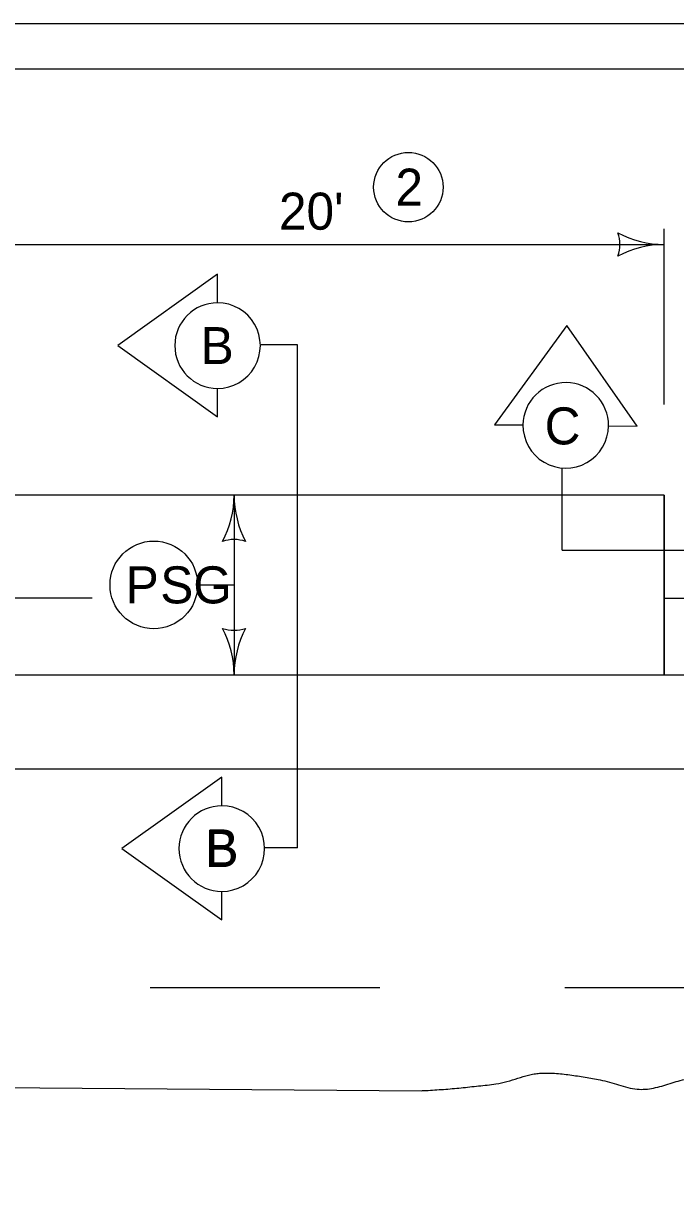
# Model space of a CAD drawing. Extents: x 8045 to 81668, y 6217 to 16762.
# Drawn here: x 11528 to 11810, y 9440 to 9944 of the extents above; entities that cross this region are included whole.
import ezdxf

# ---------------------------------------------------------------- set-up
doc = ezdxf.new("R2010")
doc.units = 0
for name, color, linetype in [('dsnCellElements', 7, 'Continuous'), ('dsnStdDimension', 7, 'Continuous'), ('dsnStdLabel', 7, 'Continuous'), ('dsnStdSection', 7, 'Continuous'), ('Level 4', 7, 'Continuous'), ('Level 8', 7, 'Continuous')]:
    doc.layers.add(name, color=color, linetype=linetype)

msp = doc.modelspace()

# ---------------------------------------------------------------- linework, layer by layer
at = {"layer": 'dsnCellElements'}
for p, q in [((11805.49, 9779.31), (11805.49, 9855.32)), ((11805.49, 9779.31), (11805.49, 9855.32)), ((11500.75, 9848.49), (11805.49, 9848.49)), ((11619.58, 9740.23), (11619.58, 9662.65)), ((11619.58, 9740.23), (11619.58, 9662.65)), ((11603.82, 9701.44), (11619.58, 9701.44)), ((11603.82, 9701.44), (11619.58, 9701.44))]:
    msp.add_line(p, q, dxfattribs=at)
msp.add_circle((11584.89, 9701.44), 18.93, dxfattribs=at)
msp.add_circle((11584.89, 9701.44), 18.93, dxfattribs=at)
for centre, radius, start, end in [((11769.86, 9848.49), 16.42, 342.2666, 17.7334), ((11805.49, 9890.99), 42.5, 241.9275, 270), ((11769.86, 9848.49), 16.42, 342.2666, 17.7334), ((11805.49, 9890.99), 42.5, 241.9275, 270), ((11805.49, 9805.99), 42.5, 90, 118.0725), ((11805.49, 9805.99), 42.5, 90, 118.0725), ((11577.08, 9740.23), 42.5, 331.9275, 0), ((11577.08, 9740.23), 42.5, 331.9275, 0), ((11662.08, 9740.23), 42.5, 180, 208.0725), ((11662.08, 9740.23), 42.5, 180, 208.0725), ((11619.58, 9704.6), 16.42, 72.2666, 107.7334), ((11619.58, 9704.6), 16.42, 72.2666, 107.7334), ((11619.58, 9698.29), 16.42, 252.2666, 287.7333), ((11577.08, 9662.65), 42.5, 360, 28.0725), ((11619.58, 9698.29), 16.42, 252.2666, 287.7333), ((11577.08, 9662.65), 42.5, 360, 28.0725), ((11662.08, 9662.65), 42.5, 151.9275, 180), ((11662.08, 9662.65), 42.5, 151.9275, 180)]:
    msp.add_arc(centre, radius, start, end, dxfattribs=at)
at = {"layer": 'dsnStdDimension'}
msp.add_line((10152.18, 9924.36), (13247.87, 9924.36), dxfattribs=at)
at = {"layer": 'dsnStdLabel'}
for p, q in [((11805.49, 9740.23), (11500.75, 9740.23)), ((11805.49, 9740.23), (11500.75, 9740.23)), ((11805.49, 9740.23), (11805.49, 9662.65)), ((11805.49, 9662.65), (11805.49, 9740.23)), ((11805.49, 9695.63), (11983.38, 9695.63)), ((10347.65, 9662.65), (11995.12, 9662.65)), ((11500.75, 9662.65), (11805.49, 9662.65)), ((10368.86, 9622), (11982.65, 9622)), ((11583.37, 9527.54), (11682.54, 9527.54)), ((11762.54, 9527.54), (11861.71, 9527.54)), ((11371.34, 9485.38), (11700.54, 9482.92))]:
    msp.add_line(p, q, dxfattribs=at)
msp.add_circle((11584.89, 9701.44), 18.93, dxfattribs=at)
msp.add_spline([(11700.54, 9482.92), (11702.54, 9483.03), (11710.11, 9483.51), (11717.68, 9484.17), (11725.23, 9484.98), (11732.76, 9485.88), (11737.51, 9486.88), (11742.19, 9488.32), (11746.86, 9489.68), (11749.21, 9490.17), (11751.58, 9490.44), (11758.12, 9490.43), (11764.71, 9489.77), (11771.29, 9488.74), (11777.81, 9487.59), (11781.82, 9486.65), (11785.79, 9485.45), (11789.77, 9484.32), (11793.78, 9483.6), (11797.32, 9483.57), (11800.87, 9484.07), (11807.98, 9486), (11815.12, 9488.01), (11822.29, 9488.73), (11836.82, 9487.76), (11851.37, 9486.45), (11858.09, 9485.63), (11864.79, 9484.64), (11871.49, 9483.7), (11878.17, 9483.03), (11883.92, 9483.59), (11889.6, 9485.42), (11895.26, 9487.47), (11900.98, 9488.73), (11908.48, 9489.24), (11916.08, 9489.37), (11927.47, 9488.67), (11931.2, 9488.16), (11938.22, 9486.34), (11945.12, 9483.78), (11952.04, 9481.41), (11959.14, 9480.18), (11980.25, 9479.17)], degree=3, dxfattribs=at)
at = {"layer": 'dsnStdSection'}
msp.add_lwpolyline([(10132.52, 9944.02), (13267.53, 9944.02), (13267.53, 7924.02), (10132.52, 7924.02)], close=True, dxfattribs=at)
at = {"layer": 'Level 4'}
for p, q in [((11647.01, 9805.1), (11631.23, 9805.1)), ((11647.01, 9805.1), (11631.23, 9805.1)), ((11647.01, 9587.81), (11647.01, 9805.1)), ((11647.01, 9587.81), (11647.01, 9805.1)), ((11761.44, 9716.47), (11761.44, 9751.91)), ((11761.44, 9716.47), (11761.44, 9751.91)), ((11761.44, 9716.47), (11849.54, 9716.47)), ((11761.44, 9716.47), (11849.54, 9716.47)), ((11558.3, 9695.63), (10526.39, 9695.63)), ((11647.01, 9587.81), (11633.05, 9587.81)), ((11647.01, 9587.81), (11633.05, 9587.81))]:
    msp.add_line(p, q, dxfattribs=at)
for points in [[(11612.44, 9823.28), (11612.44, 9835.61), (11569.31, 9804.8), (11612.44, 9773.99), (11612.44, 9786.31)], [(11781.41, 9770.18), (11793.73, 9770.07), (11763.32, 9813.48), (11732.11, 9770.63), (11744.44, 9770.52)], [(11614.26, 9606), (11614.26, 9618.32), (11571.13, 9587.51), (11614.26, 9556.7), (11614.26, 9569.02)]]:
    msp.add_lwpolyline(points, dxfattribs=at)
for centre, start, end in [((11612.44, 9804.8), 90.0008, 269.9992), ((11612.44, 9804.8), 269.9992, 90.0008), ((11762.92, 9770.35), 359.4792, 179.4775), ((11762.92, 9770.35), 179.4775, 359.4792), ((11614.26, 9587.51), 90.0008, 269.9992), ((11614.26, 9587.51), 269.9992, 90.0008)]:
    msp.add_arc(centre, 18.49, start, end, dxfattribs=at)
at = {"layer": 'Level 8'}
msp.add_circle((11694.9, 9873.25), 15, dxfattribs=at)

# ---------------------------------------------------------------- texts
at = {"layer": 'dsnCellElements'}
for s, p in [("20'", (11638.99, 9854.88)), ("20'", (11638.99, 9854.88)), ('P', (11572.76, 9693.44)), ('P', (11572.76, 9693.44)), ('SG', (11587.68, 9693.44)), ('SG', (11587.68, 9693.44))]:
    msp.add_text(s, height=16, dxfattribs=at).set_placement(p)
at = {"layer": 'Level 4'}
for s, p in [('B', (11605.17, 9796.8)), ('B', (11605.17, 9796.8)), ('C', (11753.81, 9762.12)), ('C', (11753.81, 9762.12)), ('B', (11606.99, 9579.51)), ('B', (11606.99, 9579.51)), ('B', (11607.26, 9579.81)), ('B', (11607.26, 9579.81))]:
    msp.add_text(s, height=16, dxfattribs=at).set_placement(p)
at = {"layer": 'Level 8'}
msp.add_text('2', height=16, dxfattribs=at).set_placement((11689.32, 9865.25))

doc.saveas('drawing.dxf')
